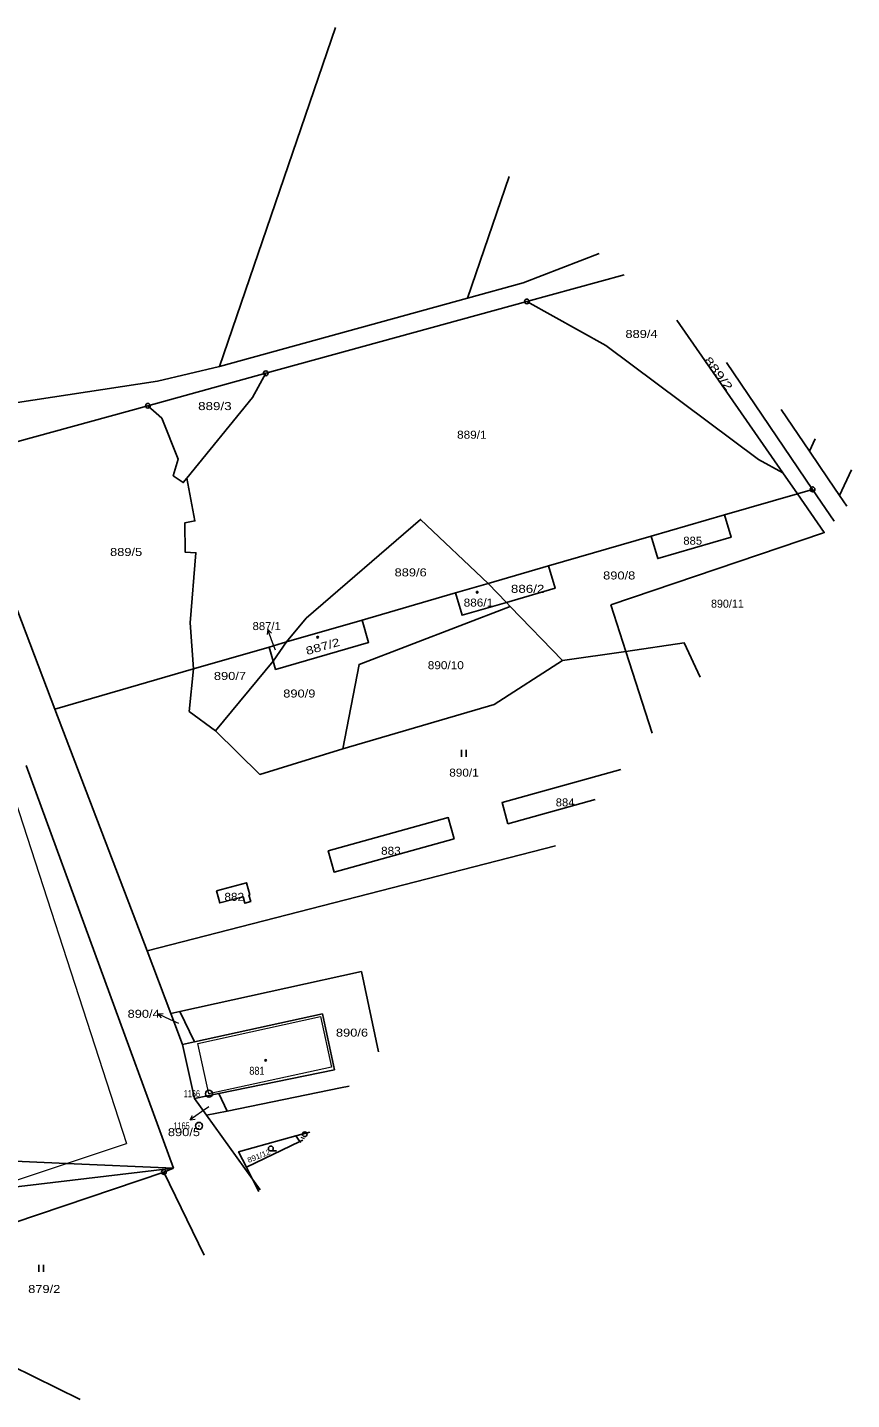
# Model space of a CAD drawing. Extents: x -546984 to -546090, y -1194931 to -1194069.
# Drawn here: x -546264.7 to -546089.8, y -1194493.2 to -1194201.8 of the extents above; entities that cross this region are included whole.
import ezdxf
from ezdxf.enums import TextEntityAlignment as Align

# ---------------------------------------------------------------- set-up
doc = ezdxf.new("R2010")
doc.units = 0
doc.header["$LTSCALE"] = 0.68
for name, color, linetype, lineweight in [('1', 7, 'Continuous', 25), ('3', 7, 'Continuous', 25), ('4', 7, 'Continuous', 13), ('5', 7, 'Continuous', 25), ('7', 7, 'Continuous', 13), ('8', 7, 'Continuous', 25)]:
    doc.layers.add(name, color=color, linetype=linetype, lineweight=lineweight)
doc.layers.add('2', color=7, linetype='Continuous')

msp = doc.modelspace()

# ---------------------------------------------------------------- linework, layer by layer
at = {"layer": '1'}
for p, q in [((-546223.97, -1194273.81), (-546199.306, -1194201.804)), ((-546171.3, -1194259.32), (-546162.434, -1194233.435)), ((-546098.06, -1194299.9), (-546116.34, -1194272.977)), ((-546098.72, -1194291.81), (-546097.498, -1194289.141)), ((-546092.32, -1194301.23), (-546089.794, -1194295.75)), ((-546116.74, -1194305.32), (-546101.3, -1194300.83)), ((-546101.3, -1194300.83), (-546098.06, -1194299.9)), ((-546098.06, -1194299.9), (-546093.48, -1194306.64)), ((-546090.782, -1194303.495), (-546092.32, -1194301.23)), ((-546116.74, -1194305.32), (-546132.3, -1194309.84)), ((-546154.1, -1194316.17), (-546132.3, -1194309.84)), ((-546095.577, -1194309.084), (-546095.58, -1194309.08)), ((-546193.67, -1194327.65), (-546173.84, -1194321.89)), ((-546166.92, -1194319.89), (-546173.84, -1194321.89)), ((-546137.68, -1194334.31), (-546140.86, -1194324.4)), ((-546193.67, -1194327.65), (-546209.72, -1194332.31)), ((-546224.8, -1194351.2), (-546212.56, -1194336.41)), ((-546264.98, -1194358.54), (-546233.72, -1194444.1)), ((-546162.72, -1194370.92), (-546144.208, -1194365.772)), ((-546239.33, -1194397.92), (-546152.634, -1194375.595)), ((-546234.29, -1194411.2), (-546239.33, -1194397.92)), ((-546234.29, -1194411.2), (-546231.77, -1194417.81)), ((-546206.87, -1194438.39), (-546207.73, -1194437.22)), ((-546206.247, -1194438.089), (-546206.87, -1194438.39)), ((-546235.74, -1194444.89), (-546227.199, -1194462.513)), ((-546216.97, -1194446.37), (-546215.622, -1194449.018)), ((-546216.97, -1194446.37), (-546215.318, -1194448.664))]:
    msp.add_line(p, q, dxfattribs=at)
for points in [[(-546223.97, -1194273.81), (-546237.14, -1194276.93), (-546278.51, -1194283.23), (-546280.55, -1194282.82), (-546289.26, -1194259.3), (-546295.56, -1194244.05), (-546298.03, -1194240.43)], [(-546143.337, -1194249.818), (-546159.48, -1194256.06), (-546171.3, -1194259.32), (-546223.97, -1194273.81)], [(-546214.13, -1194275.26), (-546158.7, -1194260), (-546138.085, -1194254.323)], [(-546104.37, -1194296.4), (-546109.55, -1194293.53), (-546141.93, -1194269.38), (-546158.7, -1194260)], [(-546126.852, -1194263.959), (-546104.37, -1194296.4), (-546101.3, -1194300.83)], [(-546239.33, -1194397.92), (-546258.87, -1194346.57), (-546279.19, -1194293.17), (-546290.97, -1194266.91)], [(-546279.19, -1194293.17), (-546239.15, -1194282.15), (-546214.13, -1194275.26)], [(-546214.13, -1194275.26), (-546216.95, -1194280.43), (-546230.85, -1194297.51)], [(-546239.15, -1194282.15), (-546236.18, -1194284.81), (-546232.74, -1194293.49), (-546233.76, -1194297.03), (-546231.64, -1194298.48), (-546230.85, -1194297.51)], [(-546092.32, -1194301.23), (-546094.75, -1194297.65), (-546098.72, -1194291.81), (-546104.762, -1194282.909)], [(-546230.85, -1194297.51), (-546229.16, -1194306.61), (-546231.34, -1194307.02), (-546231.23, -1194313.25), (-546228.95, -1194313.35), (-546230.17, -1194328.25), (-546229.47, -1194338.04), (-546213.44, -1194333.39)], [(-546140.86, -1194324.4), (-546095.97, -1194309.21), (-546095.58, -1194309.08), (-546101.3, -1194300.83)], [(-546209.72, -1194332.31), (-546205.52, -1194327.24), (-546181.27, -1194306.29), (-546166.92, -1194319.89)], [(-546132.3, -1194309.84), (-546130.92, -1194314.59), (-546115.37, -1194310.07), (-546116.74, -1194305.32)], [(-546163.05, -1194323.92), (-546152.72, -1194320.92), (-546154.1, -1194316.17), (-546166.92, -1194319.89)], [(-546173.84, -1194321.89), (-546172.46, -1194326.65), (-546163.05, -1194323.92), (-546166.92, -1194319.89)], [(-546197.75, -1194355.03), (-546194.33, -1194337.09), (-546162.24, -1194324.76)], [(-546163.05, -1194323.92), (-546162.24, -1194324.76), (-546151.17, -1194336.24)], [(-546212.56, -1194336.41), (-546212.06, -1194338.14), (-546192.29, -1194332.4), (-546193.67, -1194327.65)], [(-546121.934, -1194339.808), (-546125.29, -1194332.53), (-546137.68, -1194334.31)], [(-546151.17, -1194336.24), (-546165.62, -1194345.6), (-546197.75, -1194355.03)], [(-546132.1, -1194351.658), (-546137.68, -1194334.31), (-546151.17, -1194336.24)], [(-546224.8, -1194351.2), (-546230.4, -1194347.05), (-546229.47, -1194338.04), (-546258.87, -1194346.57)], [(-546197.75, -1194355.03), (-546215.37, -1194360.43), (-546224.8, -1194351.2)], [(-546138.743, -1194359.402), (-546163.97, -1194366.42), (-546162.72, -1194370.92)], [(-546190.171, -1194419.35), (-546193.82, -1194402.31), (-546209.87, -1194405.84), (-546232.34, -1194410.77)], [(-546229.26, -1194417.26), (-546232.34, -1194410.77), (-546234.29, -1194411.2)], [(-546222.3, -1194431.94), (-546198.3, -1194427.01), (-546196.409, -1194426.622)], [(-546229.27, -1194429.28), (-546226.71, -1194432.84), (-546222.3, -1194431.94), (-546224.07, -1194428.21)], [(-546226.71, -1194432.84), (-546216.97, -1194446.37), (-546218.24, -1194443.87)], [(-546218.24, -1194443.87), (-546219.89, -1194440.63), (-546207.73, -1194437.22), (-546204.791, -1194436.393)], [(-546206.701, -1194438.619), (-546206.87, -1194438.39), (-546218.24, -1194443.87)], [(-546312.37, -1194445.5), (-546307.85, -1194444.66), (-546291.01, -1194441.53), (-546256.43, -1194443.08), (-546233.72, -1194444.1)], [(-546233.72, -1194444.1), (-546273.66, -1194448.8), (-546294.44, -1194451.24), (-546307.01, -1194447.22), (-546312.37, -1194445.5)], [(-546307.77, -1194469.14), (-546299.75, -1194466.54), (-546235.74, -1194444.89), (-546233.72, -1194444.1)], [(-546253.531, -1194493.208), (-546278.01, -1194481.18), (-546297.58, -1194488.58)]]:
    msp.add_lwpolyline(points, dxfattribs=at)
for points in [[(-546212.56, -1194336.41), (-546209.72, -1194332.31), (-546213.44, -1194333.39)], [(-546174.13, -1194374.09), (-546175.38, -1194369.6), (-546200.86, -1194376.69), (-546199.61, -1194381.18)], [(-546224.59, -1194385.14), (-546223.89, -1194387.75), (-546218.95, -1194386.43), (-546218.58, -1194387.79), (-546217.33, -1194387.46), (-546217.69, -1194386.09), (-546217.52, -1194386.05), (-546218.21, -1194383.44)], [(-546224.07, -1194428.21), (-546199.54, -1194423.18), (-546202.09, -1194411.29), (-546229.26, -1194417.26), (-546231.77, -1194417.81), (-546229.27, -1194429.28)]]:
    msp.add_lwpolyline(points, close=True, dxfattribs=at)
at = {"layer": '3'}
for p, q in [((-546172.601, -1194356.72), (-546172.601, -1194355.22)), ((-546171.6, -1194356.72), (-546171.6, -1194355.22)), ((-546205.865, -1194437.37), (-546205.629, -1194437.37)), ((-546213.055, -1194440.39), (-546211.883, -1194440.39)), ((-546262.331, -1194466.07), (-546262.331, -1194464.57)), ((-546261.33, -1194466.07), (-546261.33, -1194464.57))]:
    msp.add_line(p, q, dxfattribs=at)
for centre in [(-546205.8652, -1194436.8674), (-546213.0552, -1194439.8874)]:
    msp.add_circle(centre, 0.5025, dxfattribs=at)
at = {"layer": '4'}
msp.add_line((-546226.19, -1194428.25), (-546228.55, -1194417.6), dxfattribs=at)
for points in [[(-546276.08, -1194339.07), (-546273.25, -1194347.79), (-546243.71, -1194438.86)], [(-546228.55, -1194417.6), (-546202.48, -1194411.87), (-546200.16, -1194422.64), (-546226.19, -1194428.25)], [(-546273.66, -1194448.8), (-546256.43, -1194443.08), (-546243.71, -1194438.86)]]:
    msp.add_lwpolyline(points, dxfattribs=at)
at = {"layer": '5'}
for centre in [(-546169.2568, -1194321.7492), (-546203.0968, -1194331.3092), (-546214.1368, -1194421.1792)]:
    msp.add_circle(centre, 0.175, dxfattribs=at)
at = {"layer": '7'}
for p, q in [((-546213.706, -1194329.64), (-546213.834, -1194330.752)), ((-546237.06, -1194411.282), (-546236.364, -1194412.159)), ((-546230.208, -1194433.831), (-546229.101, -1194433.667)), ((-546206.68, -1194437.49), (-546205.97, -1194437.767))]:
    msp.add_line(p, q, dxfattribs=at)
for points in [[(-546212.09, -1194334.07), (-546212.68, -1194332.46), (-546213.706, -1194329.64), (-546212.893, -1194330.41)], [(-546232.6, -1194413.36), (-546234.34, -1194412.55), (-546237.06, -1194411.282), (-546235.941, -1194411.251)], [(-546226.22, -1194431.05), (-546227.75, -1194432.11), (-546230.208, -1194433.831), (-546229.675, -1194432.847)]]:
    msp.add_lwpolyline(points, dxfattribs=at)
at = {"layer": '8'}
for centre, radius in [((-546158.7, -1194259.9999), 0.5), ((-546158.7, -1194259.9999), 0.0303), ((-546214.13, -1194275.2599), 0.5), ((-546214.13, -1194275.2599), 0.0303), ((-546239.15, -1194282.1499), 0.5), ((-546239.15, -1194282.1499), 0.0303), ((-546098.06, -1194299.8999), 0.5), ((-546098.06, -1194299.8999), 0.0303), ((-546226.19, -1194428.2498), 0.75), ((-546226.19, -1194428.2498), 0.03), ((-546228.29, -1194435.0898), 0.75), ((-546228.29, -1194435.0898), 0.03), ((-546235.74, -1194444.8899), 0.5), ((-546235.74, -1194444.8899), 0.0303)]:
    msp.add_circle(centre, radius, dxfattribs=at)

# ---------------------------------------------------------------- texts
at = {"layer": '2'}
for s, width, p in [('889/4', 1.2, (-546137.79, -1194267.75)), ('889/3', 1.25, (-546228.486, -1194283.07)), ('889/1', 1.1, (-546173.52, -1194289.15)), ('889/5', 1.2, (-546247.18, -1194314.05)), ('889/6', 1.2, (-546186.79, -1194318.39)), ('890/8', 1.2, (-546142.52, -1194319.04)), ('886/1', 1.1, (-546172.12, -1194324.8)), ('890/10', 1.1, (-546179.74, -1194338.1)), ('890/7', 1.2, (-546225.14, -1194340.38)), ('890/9', 1.2, (-546210.42, -1194344.11)), ('890/1', 1.1, (-546175.18, -1194360.91)), ('890/6', 1.2, (-546199.24, -1194416.13)), ('879/2', 1.2, (-546264.56, -1194470.58))]:
    msp.add_text(s, height=1.7, dxfattribs=dict(at, width=width)).set_placement(p)
for s, height, rotation, width, p in [('889/2', 1.7, 307, 1.45, (-546121.198, -1194272.521)), ('887/2', 1.7, 16, 1.3, (-546205.355, -1194335.107)), ('891/12', 1.14, 22, 1.1, (-546217.756, -1194442.958))]:
    msp.add_text(s, height=height, rotation=rotation, dxfattribs=dict(at, width=width)).set_placement(p)
for s, width, p in [('885', 1.05, (-546123.5095, -1194311.66)), ('886/2', 1.25, (-546158.543, -1194321.88)), ('887/1', 1.05, (-546213.935, -1194329.79)), ('884', 1.05, (-546150.5865, -1194367.24)), ('883', 1.1, (-546187.5695, -1194377.51)), ('882', 1.1, (-546220.823, -1194387.29)), ('881', 0.85, (-546216.0045, -1194424.23))]:
    msp.add_text(s, height=1.7, dxfattribs=dict(at, width=width)).set_placement(p, align=Align.CENTER)
msp.add_text('890/11', height=1.7, dxfattribs=at).set_placement((-546119.62, -1194325.03))
at = {"layer": '2', "width": 1.2}
for s, p in [('890/4', (-546236.633, -1194412.13)), ('890/5', (-546228.079, -1194437.263))]:
    msp.add_text(s, height=1.7, dxfattribs=at).set_placement(p, align=Align.RIGHT)
at = {"layer": '8', "width": 0.75}
for s, p in [('1166', (-546228.084, -1194429)), ('1165', (-546230.268, -1194435.84))]:
    msp.add_text(s, height=1.5, dxfattribs=at).set_placement(p, align=Align.RIGHT)

doc.saveas('drawing.dxf')
